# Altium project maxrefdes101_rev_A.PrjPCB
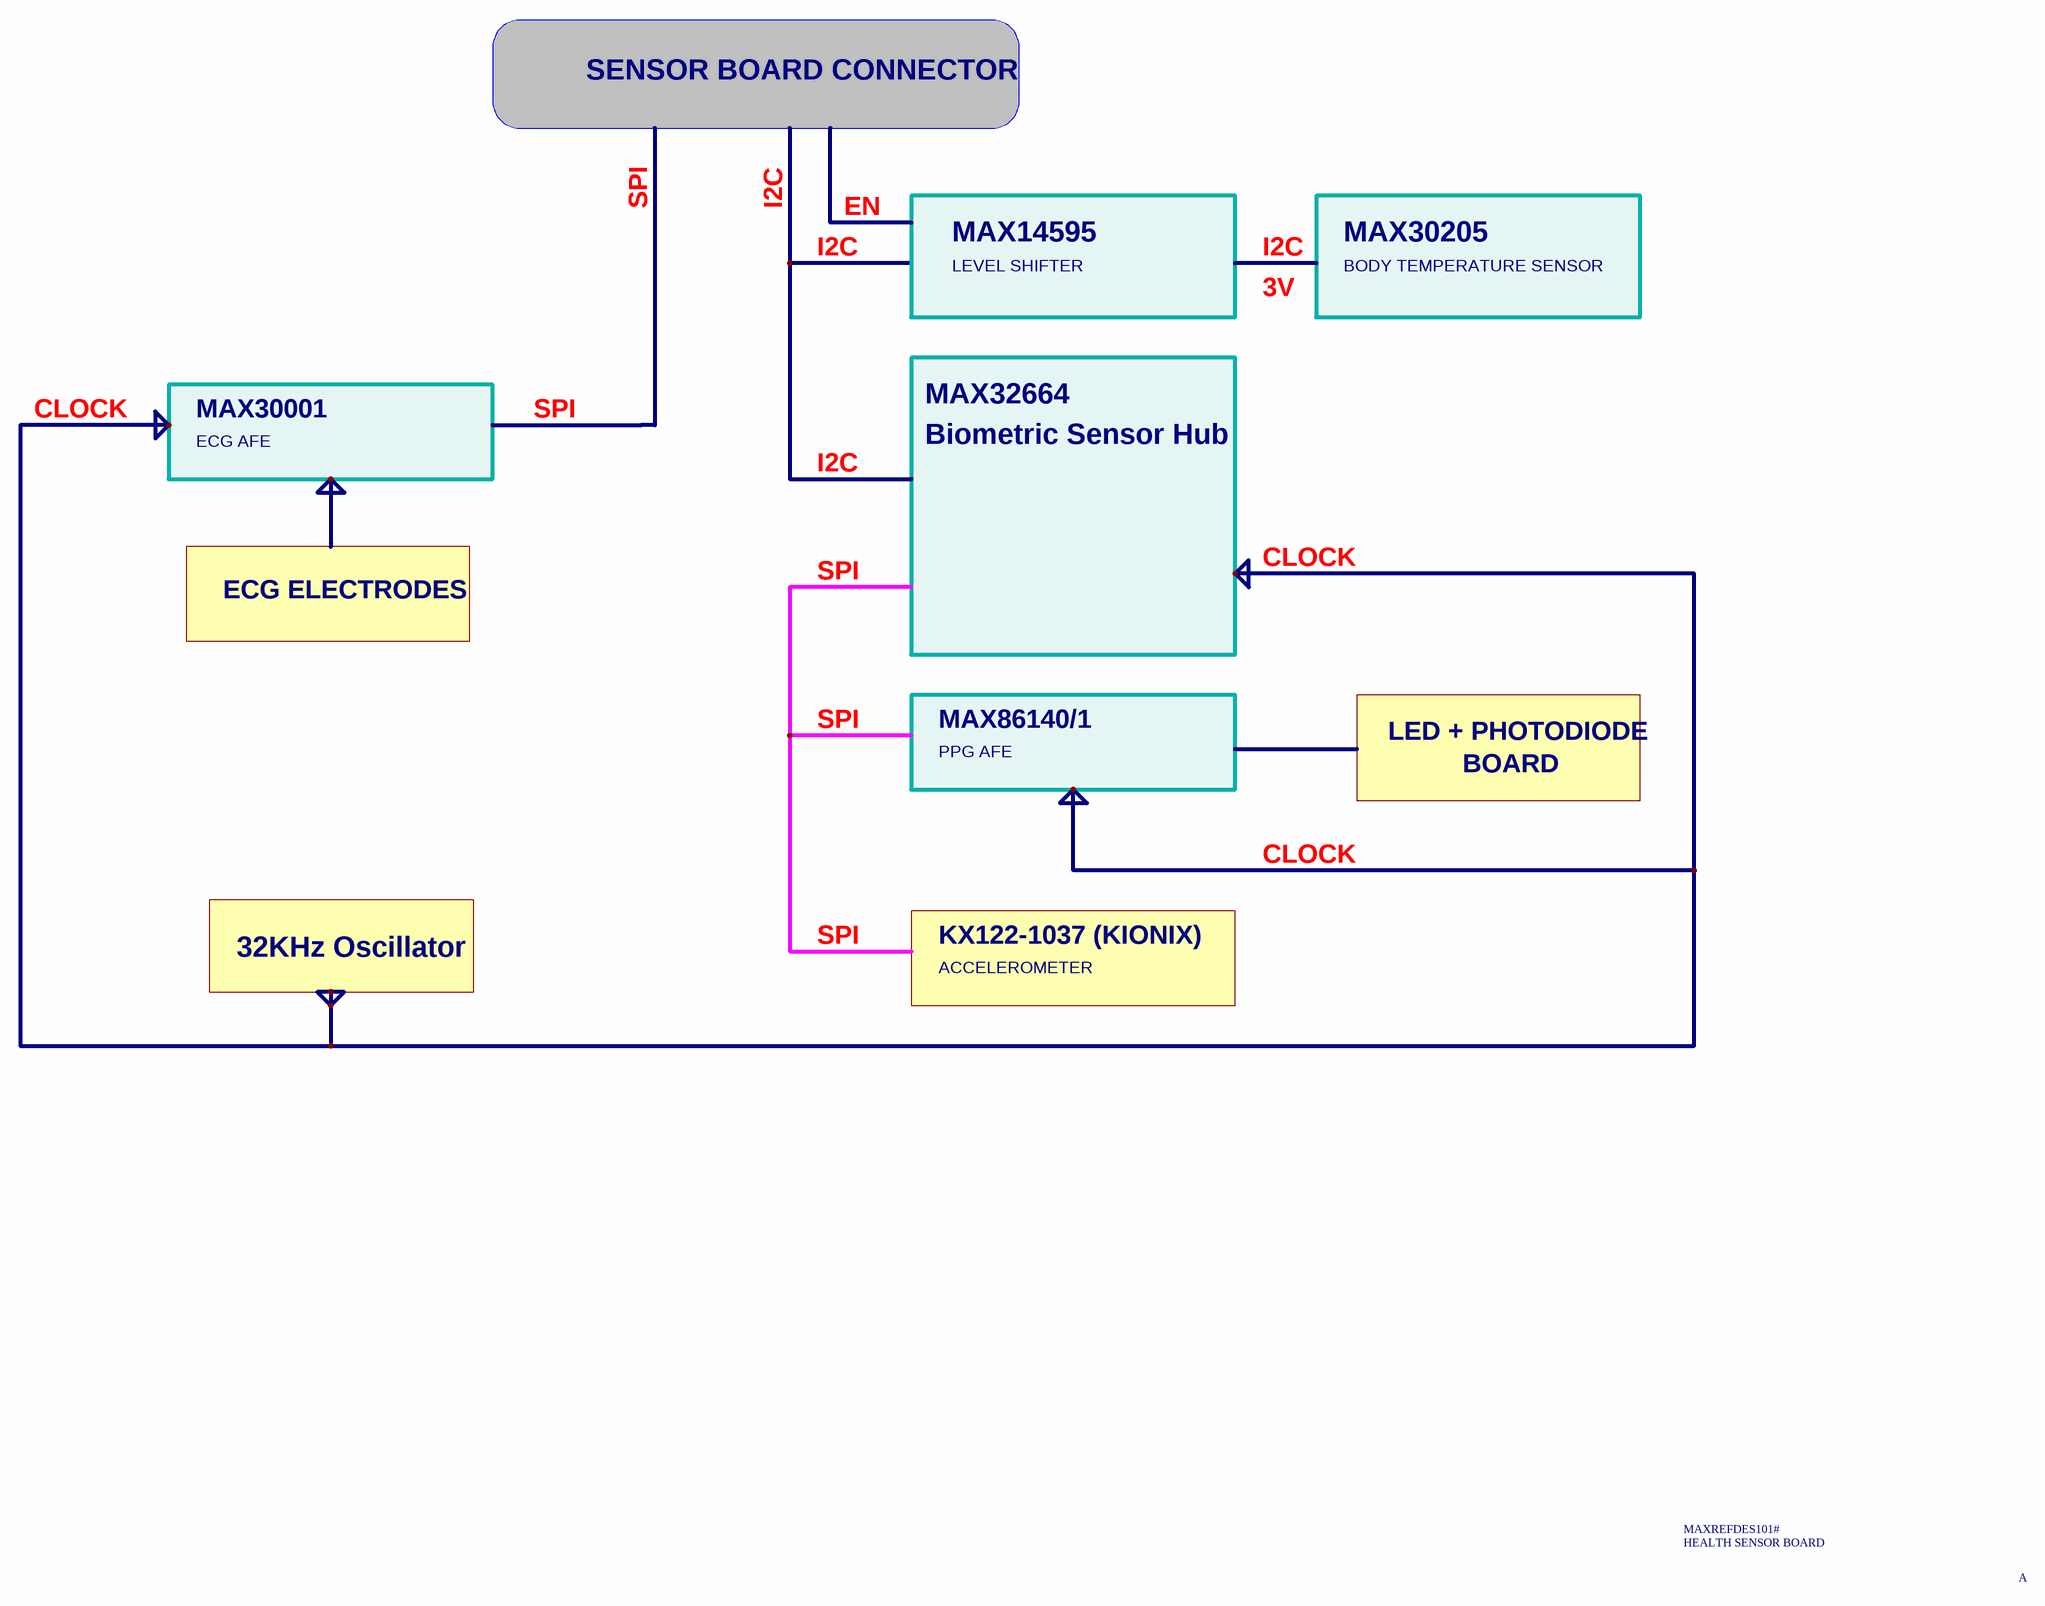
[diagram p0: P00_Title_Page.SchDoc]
2 sheets, 87 parts. Net scope: global (net labels, ports and power ports of the same name join across sheets).
Board file: maxrefdes101_rev_A.PcbDoc
Sheets:
  P00_Title_Page.SchDoc
  P01_Sensors.SchDoc

## Sheet P00_Title_Page.SchDoc
size C; PageSetup: Record=PageOptions¦CenterHorizontal=True¦CenterVertical=True¦PrintScale=0.54¦XCorrection=1.00¦YCorrection=1.00¦PrintKind=1¦BorderSize=5000000¦LeftOffset=0¦BottomOffset=0¦Orientation=2¦PaperLength=1000¦PaperWidth=1000¦Scale=100¦PaperSource=7¦PrintQuality=600¦MediaType=1¦DitherType=10¦PrintScaleMode=1¦PaperKind=Letter¦PaperIndex=1

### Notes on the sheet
- SENSOR BOARD CONNECTOR
- SPI
- I2C
- EN
- MAX14595
- LEVEL SHIFTER
- MAX30205
- BODY TEMPERATURE SENSOR
- 3V
- MAX32664
- CLOCK
- MAX30001
- ECG AFE
- Biometric Sensor Hub
- ECG ELECTRODES
- MAX86140/1
- LED + PHOTODIODE
- PPG AFE
- BOARD
- KX122-1037 (KIONIX)
- 32KHz Oscillator
- ACCELEROMETER
- MAXREFDES101#
- HEALTH SENSOR BOARD
- A

## Sheet P01_Sensors.SchDoc
size C; PageSetup: Record=PageOptions¦CenterHorizontal=True¦CenterVertical=True¦PrintScale=0.54¦XCorrection=1.00¦YCorrection=1.00¦PrintKind=0¦BorderSize=5000000¦LeftOffset=0¦BottomOffset=0¦Orientation=2¦PaperLength=1000¦PaperWidth=1000¦Scale=100¦PaperSource=7¦PrintQuality=-3¦MediaType=1¦DitherType=10¦PrintScaleMode=1¦PaperKind=Letter¦PaperIndex=1
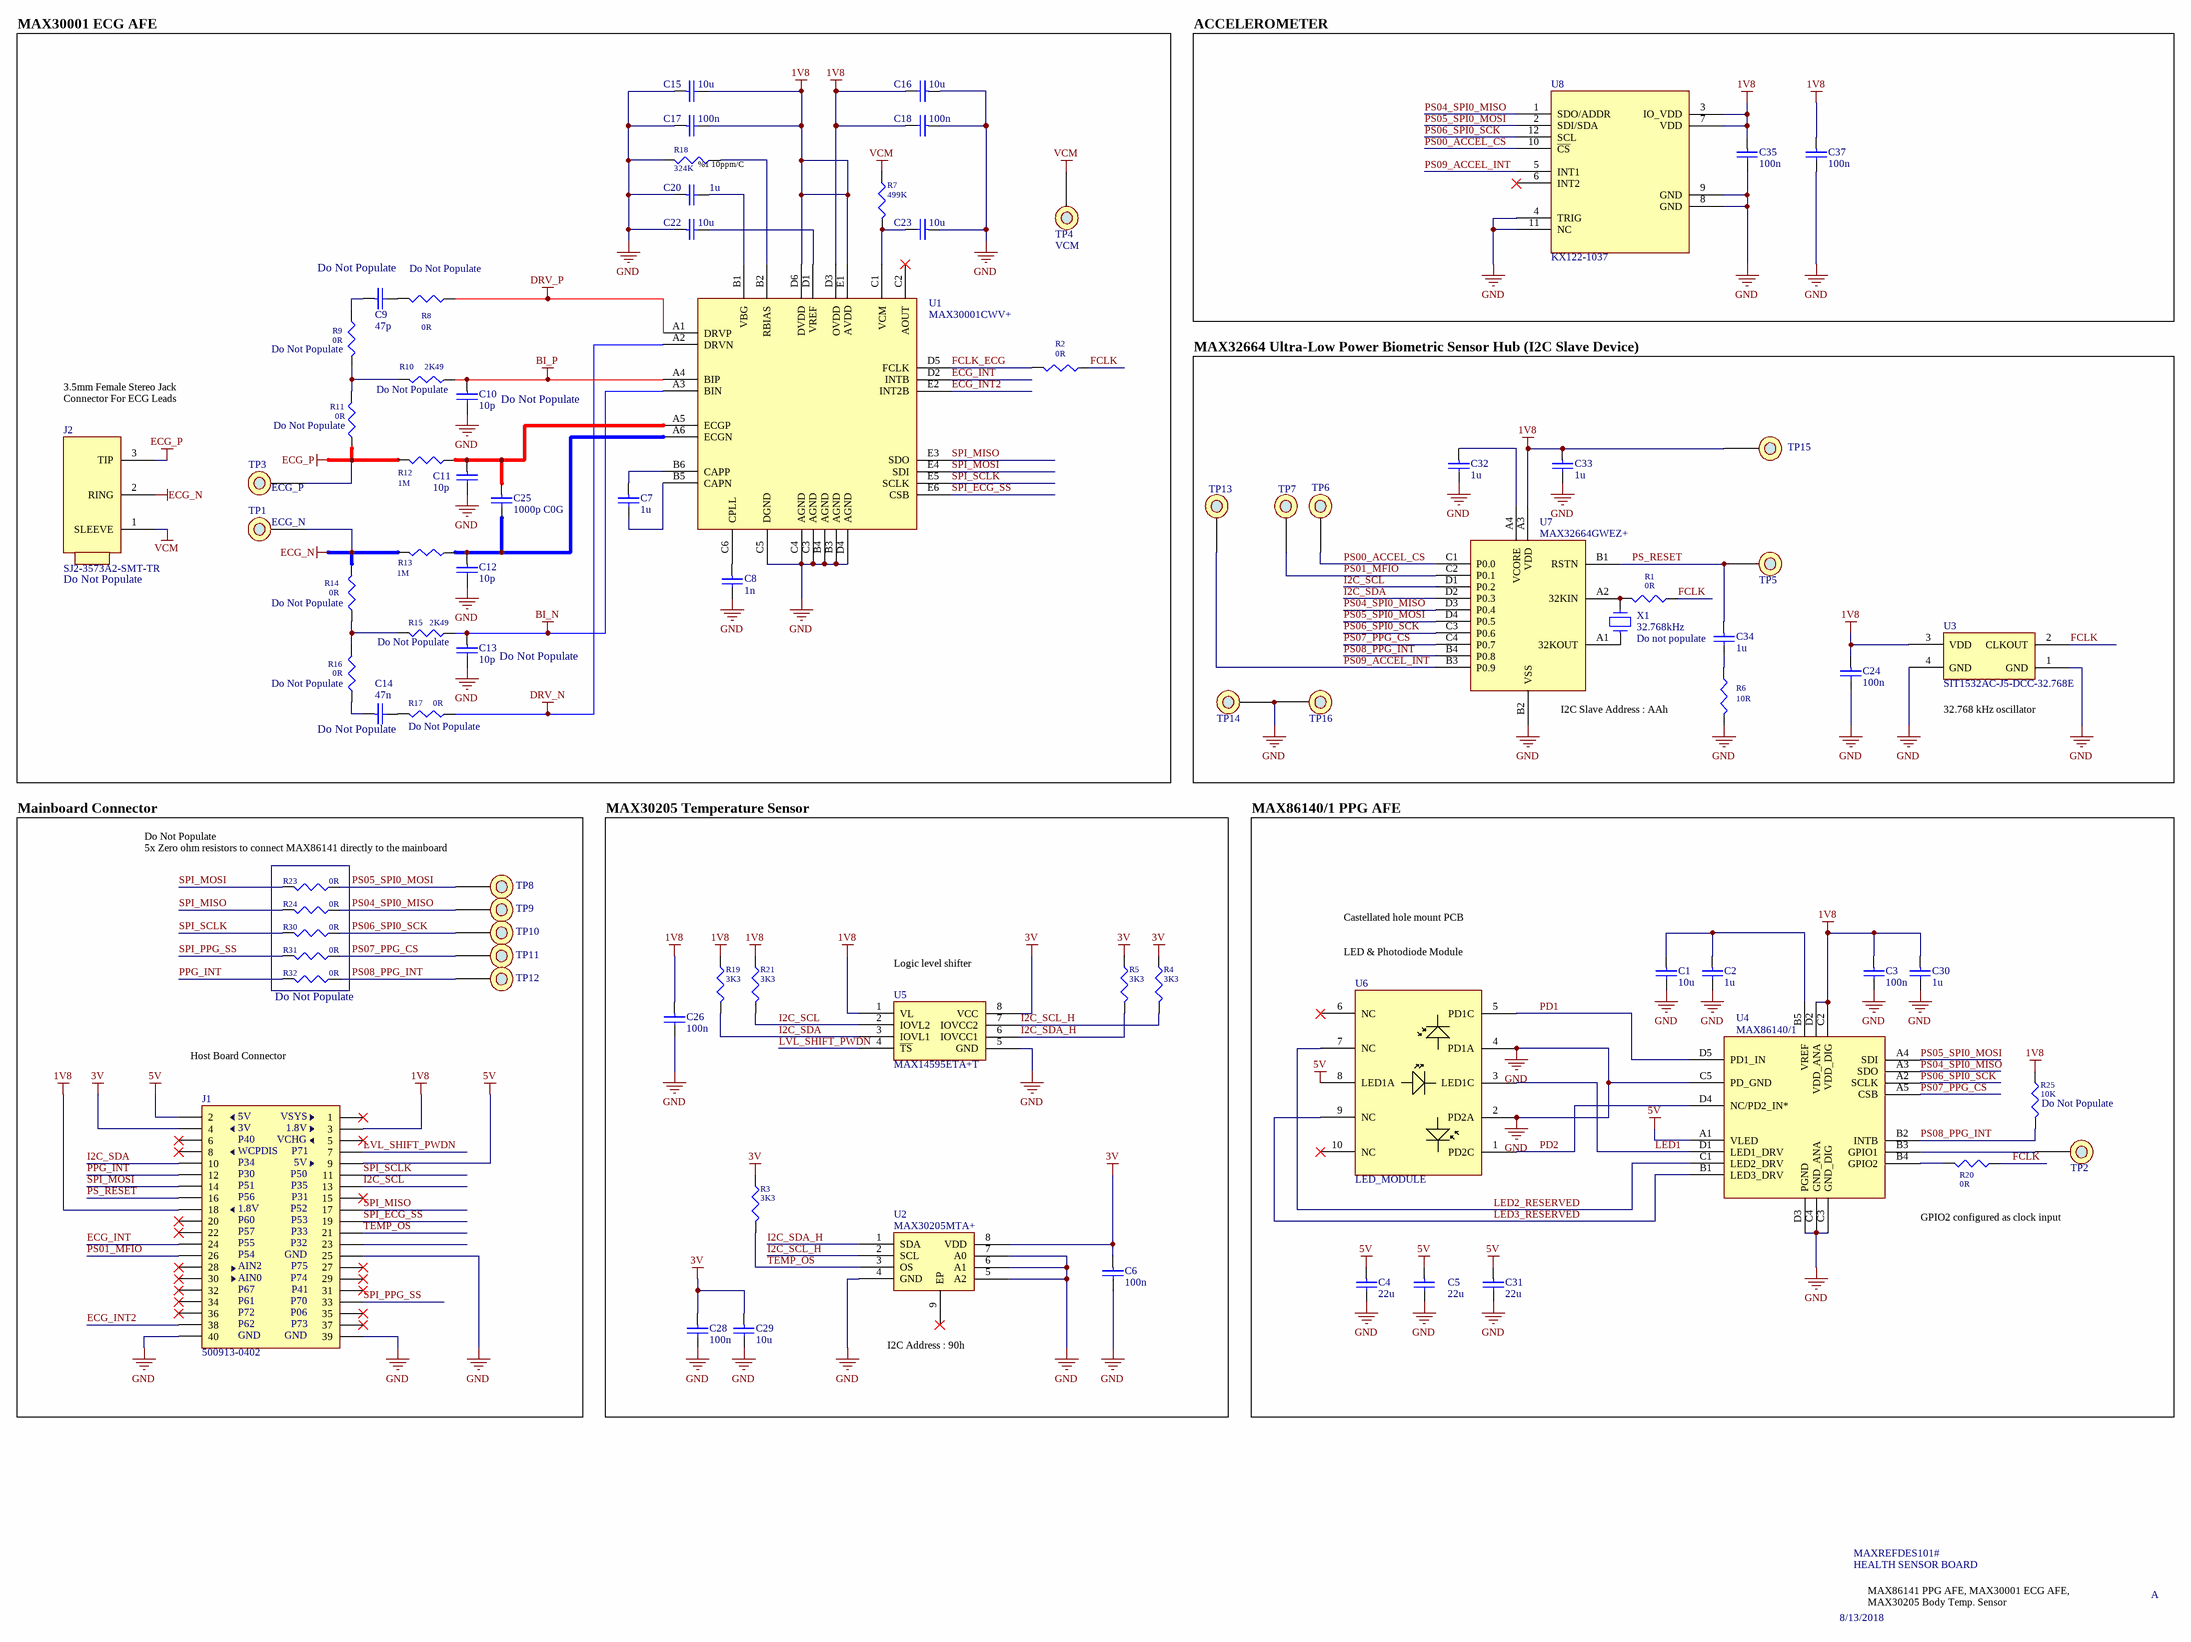
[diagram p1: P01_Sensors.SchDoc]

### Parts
C1  10u  [CAPACITOR_SMD_0402]
C2  1u  [CAPACITOR_SMD_0603]
C3  100n  [CAPACITOR_SMD_0603]
C4  22u  [CAPACITOR_SMD_0402]
C5  22u  [CAPACITOR_SMD_0402]
C6  100n  [CAPACITOR_SMD_0402]
C7  1u  [CAPACITOR_SMD_0603]
C8  1n  [CAPACITOR_SMD_0201]
C9  47p  [CAPACITOR_SMD_0201]
C10  10p  [CAPACITOR_SMD_0201]
C11  10p  [CAPACITOR_SMD_0201]
C12  10p  [CAPACITOR_SMD_0201]
C13  10p  [CAPACITOR_SMD_0201]
C14  47n  [CAPACITOR_SMD_0201]
C15  10u  [CAPACITOR_SMD_0402]
C16  10u  [CAPACITOR_SMD_0402]
C17  100n  [CAPACITOR_SMD_0201]
C18  100n  [CAPACITOR_SMD_0201]
C20  1u  [CAPACITOR_SMD_0201]
C22  10u  [CAPACITOR_SMD_0402]
C23  10u  [CAPACITOR_SMD_0402]
C24  100n  [CAPACITOR_SMD_0402]
C25  1000p C0G  [CAPACITOR_SMD_0201]
C26  100n  [CAPACITOR_SMD_0402]
C28  100n  [CAPACITOR_SMD_0402]
C29  10u  [CAPACITOR_SMD_0402]
C30  1u  [CAPACITOR_SMD_0201]
C31  22u  [CAPACITOR_SMD_0402]
C32  1u  [CAPACITOR_SMD_0201]
C33  1u  [CAPACITOR_SMD_0201]
C34  1u  [CAPACITOR_SMD_0201]
C35  100n  [CAPACITOR_SMD_0201]
C37  100n  [CAPACITOR_SMD_0201]
J1  500913-0402  [500913-0402_MRR]
J2  SJ2-3573A2-SMT-TR  [CONN_SJ2-3573A2-SMT-TR]
R1  0R  [RESISTOR_SMD_0201]
R2  0R  [RESISTOR_SMD_0201]
R3  3K3  [RESISTOR_SMD_0402]
R4  3K3  [RESISTOR_SMD_0402]
R5  3K3  [RESISTOR_SMD_0402]
R6  10R  [RESISTOR_SMD_0201]
R7  499K  [RESISTOR_SMD_0402]
R8  0R  [RESISTOR_SMD_0201]
R9  0R  Notes: Do Not Populate  [RESISTOR_SMD_0201]
R10  2K49  Notes: Do Not Populate  [RESISTOR_SMD_0201]
R11  0R  Notes: Do Not Populate  [RESISTOR_SMD_0201]
R12  1M  [RESISTOR_SMD_0201]
R13  1M  [RESISTOR_SMD_0201]
R14  0R  Notes: Do Not Populate  [RESISTOR_SMD_0201]
R15  2K49  Notes: Do Not Populate  [RESISTOR_SMD_0201]
R16  0R  Notes: Do Not Populate  [RESISTOR_SMD_0201]
R17  0R  Notes: Do Not Populate  [RESISTOR_SMD_0201]
R18  324K  [RESISTOR_SMD_0603]
R19  3K3  [RESISTOR_SMD_0402]
R20  0R  [RESISTOR_SMD_0201]
R21  3K3  [RESISTOR_SMD_0402]
R23  0R  [RESISTOR_SMD_0201]
R24  0R  [RESISTOR_SMD_0201]
R25  10K  Notes: Do Not Populate  [RESISTOR_SMD_0201]
R30  0R  [RESISTOR_SMD_0201]
R31  0R  [RESISTOR_SMD_0201]
R32  0R  [RESISTOR_SMD_0201]
TP1  ECG_N  [TESTPOINT_SIZE_A_NO_BODY]
TP2  TestPoint  [TESTPOINT_SIZE_B]  (value not drawn)
TP3  ECG_P  [TESTPOINT_SIZE_A_NO_BODY]
TP4  VCM  [TESTPOINT_SIZE_A_NO_BODY]
TP5  RSTN  [TESTPOINT_SIZE_C]  (value not drawn)
TP6  TestPoint  [TESTPOINT_SIZE_C]  (value not drawn)
TP7  TestPoint  [TESTPOINT_SIZE_C]  (value not drawn)
TP8  TestPoint  [TESTPOINT_SIZE_B]  (value not drawn)
TP9  TestPoint  [TESTPOINT_SIZE_B]  (value not drawn)
TP10  TestPoint  [TESTPOINT_SIZE_B]  (value not drawn)
TP11  TestPoint  [TESTPOINT_SIZE_B]  (value not drawn)
TP12  TestPoint  [TESTPOINT_SIZE_B]  (value not drawn)
TP13  TestPoint  [TESTPOINT_SIZE_B]  (value not drawn)
TP14  TestPoint  [TESTPOINT_SIZE_B]  (value not drawn)
TP15  TestPoint  [TESTPOINT_SIZE_C]  (value not drawn)
TP16  TestPoint  [TESTPOINT_SIZE_B]  (value not drawn)
U1  MAX30001CWV+  [WLP30 0.5MM]
U2  MAX30205MTA+  [TDFN_3x3mm]
U3  SIT1532AC-J5-DCC-32.768E  [CSP_1.55x0.85_4pin]
U4  MAX86140/1  [WLP20_0.4mm]
U5  MAX14595ETA+T  [TDFN8]
U6  LED_MODULE  [HSP3_LEDMODULE_03]
U7  MAX32664GWEZ+  [WLP16_0.35mm]
U8  KX122-1037  [LGA-12_2x2x0.9]
X1  32.768kHz  Notes: Do not populate  [CRYSTAL_2x1.2mm]

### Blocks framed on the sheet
MAX30001 ECG AFE: C7-C18 C20 C22 C23 C25 J2 R2 R7-R18 TP1 TP3 TP4 U1
ACCELEROMETER: C35 C37 U8
Mainboard Connector: J1 R23 R24 R30-R32 TP8-TP12
MAX30205 Temperature Sensor: C6 C26 C28 C29 R3-R5 R19 R21 U2 U5
MAX86140/1 PPG AFE: C1-C5 C30 C31 R20 R25 TP2 U4 U6

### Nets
1V8: C3.1 C15.2 C16.2 C17.2 C18.2 C24.1 C26.1 C30.1 C33.1 C35.1 C37.1 J1.3 J1.18 R19.1 R21.1 R25.1 TP15.TP U1.D3(OVDD) U1.D6(DVDD) U1.E1(AVDD) U3.3(VDD) U4.C2(VDD_DIG) U4.D2(VDD_ANA) U5.1(VL) U7.A3(VDD) U8.3(IO_VDD) U8.7(VDD)
3V: C6.1 C28.1 C29.1 J1.4 R3.1 R4.1 R5.1 U2.8(VDD) U5.8(VCC)
5V: C4.1 C5.1 C31.1 J1.2 J1.9 U4.A1(VLED) U6.8(LED1A)
BI_N: C13.1 R15.1 U1.A3(BIN)
BI_P: C10.1 R10.1 U1.A4(BIP)
DRV_N: R17.1 U1.A2(DRVN)
DRV_P: R8.1 U1.A1(DRVP)
ECG_N: J2.2(RING) R13.2 R14.2 TP1.TP
ECG_P: J2.3(TIP) R11.1 R12.2 TP3.TP
GND: C1.2 C2.2 C3.2 C4.2 C5.2 C6.2 C8.2 C10.2 C11.2 C12.2 C13.2 C15.1 C16.1 C17.1 C18.1 C20.1 C22.1 C23.1 C24.2 C26.2 C28.2 C29.2 C30.2 C31.2 C32.2 C33.2 C35.2 C37.2 J1.25 J1.39 J1.40 R6.2 R18.2 TP14.TP TP16.TP U1.B3(AGND) U1.B4(AGND) U1.C3(AGND) U1.C4(AGND) U1.C5(DGND) U1.D4(AGND) U2.4(GND) U2.5(A2) U2.6(A1) U2.7(A0) U3.1(GND) U3.4(GND) U4.C3(GND_DIG) U4.C4(GND_ANA) U4.C5(PD_GND) U4.D3(PGND) U5.5(GND) U6.2(PD2A) U6.4(PD1A) U7.B2(VSS) U8.4(TRIG) U8.8(GND) U8.9(GND) U8.11(NC)
VCM: J2.1(SLEEVE) R7.1 TP4.TP
ECG_INT: J1.24 U1.D2(INTB)
ECG_INT2: J1.38 U1.E2(INT2B)
FCLK: R1.1 R2.1 R20.1 U3.2(CLKOUT)
FCLK_ECG: R2.2 U1.D5(FCLK)
I2C_SCL: J1.13 R21.2 U5.2(IOVL2) U7.D1(P0.2)
I2C_SCL_H: R4.2 U2.2(SCL) U5.7(IOVCC2)
I2C_SDA: J1.10 R19.2 U5.3(IOVL1) U7.D2(P0.3)
I2C_SDA_H: R5.2 U2.1(SDA) U5.6(IOVCC1)
LED1: U4.D1(LED1_DRV) U6.3(LED1C)
LED2_RESERVED: U4.C1(LED2_DRV) U6.7(NC)
LED3_RESERVED: U4.B1(LED3_DRV) U6.9(NC)
LVL_SHIFT_PWDN: J1.7 U5.4(~{TS})
PD1: U4.D5(PD1_IN) U6.5(PD1C)
PD2: U4.D4(NC/PD2_IN*) U6.1(PD2C)
PPG_INT: J1.12 R32.2
PS00_ACCEL_CS: TP6.TP U7.C1(P0.0) U8.10(~{CS})
PS01_MFIO: J1.26 TP7.TP U7.C2(P0.1)
PS04_SPI0_MISO: R24.1 TP9.TP U4.A3(SDO) U7.D3(P0.4) U8.1(SDO/ADDR)
PS05_SPI0_MOSI: R23.1 TP8.TP U4.A4(SDI) U7.D4(P0.5) U8.2(SDI/SDA)
PS06_SPI0_SCK: R30.1 TP10.TP U4.A2(SCLK) U7.C3(P0.6) U8.12(SCL)
PS07_PPG_CS: R31.1 TP11.TP U4.A5(CSB) U7.C4(P0.7)
PS08_PPG_INT: R25.2 R32.1 TP12.TP U4.B2(INTB) U7.B4(P0.8)
PS09_ACCEL_INT: TP13.TP U7.B3(P0.9) U8.5(INT1)
PS_RESET: C34.1 J1.16 TP5.TP U7.B1(RSTN)
SPI_ECG_SS: J1.19 U1.E6(CSB)
SPI_MISO: J1.17 R24.2 U1.E3(SDO)
SPI_MOSI: J1.14 R23.2 U1.E4(SDI)
SPI_PPG_SS: J1.33 R31.2
SPI_SCLK: J1.11 R30.2 U1.E5(SCLK)
TEMP_OS: J1.21 R3.2 U2.3(OS)
NetC1_1: C1.1 C2.1 U4.B5(VREF)
NetC7_1: C7.1 U1.B6(CAPP)
NetC7_2: C7.2 U1.B5(CAPN)
NetC8_1: C8.1 U1.C6(CPLL)
NetC9_1: C9.1 R9.1
NetC9_2: C9.2 R8.2
NetC11_1: C11.1 C25.1 R12.1 U1.A5(ECGP)
NetC12_1: C12.1 C25.2 R13.1 U1.A6(ECGN)
NetC14_1: C14.1 R16.1
NetC14_2: C14.2 R17.2
NetC20_2: C20.2 U1.B1(VBG)
NetC22_2: C22.2 U1.D1(VREF)
NetC23_2: C23.2 R7.2 U1.C1(VCM)
NetC32_1: C32.1 U7.A4(VCORE)
NetC34_2: C34.2 R6.1
NetR1_2: R1.2 U7.A2(32KIN) X1.2
NetR9_2: R9.2 R10.2 R11.2
NetR14_1: R14.1 R15.2 R16.2
NetR18_1: R18.1 U1.B2(RBIAS)
NetR20_2: R20.2 U4.B4(GPIO2)
NetTP2_TP: TP2.TP U4.B3(GPIO1)
NetU7_A1: U7.A1(32KOUT) X1.1

Not connected (* = marked no-connect by the designer): J1 1* 5* 6* 8* 15* 20* 22* 23 27* 28* 29* 30* 31* 32* 34* 35* 36* 37*; U1 C2(AOUT)*; U2 9(EP)*; U6 6(NC)* 10(NC)*; U8 6(INT2)*

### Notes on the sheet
- (near R18) %1 10ppm/C
- Do Not Populate
- MAX32664 Ultra-Low Power Biometric Sensor Hub (I2C Slave Device)
- 3.5mm Female Stereo Jack Connector For ECG Leads
- (near C10) Do Not Populate
- (near J2) Do Not Populate
- (near C13) Do Not Populate
- (near U7) I2C Slave Address : AAh
- (near U3) 32.768 kHz oscillator
- Do Not Populate
  5x Zero ohm resistors to connect MAX86141 directly to the mainboard
- Castellated hole mount PCB
- (near R32) Do Not Populate
- (near U5) Logic level shifter
- LED & Photodiode Module
- (near J1) Host Board Connector
- GPIO2 configured as clock input
- I2C Address : 90h
- MAXREFDES101#
- HEALTH SENSOR BOARD
- 8/13/2018
- MAX86141 PPG AFE, MAX30001 ECG AFE, MAX30205 Body Temp. Sensor
- A

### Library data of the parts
C1 C15 C16 C22 C23 C29 = CAP_0402_10u: CAP CER 10UF 4V X5R 0402; Manufacturer: Murata Electronics North America; Manufacturer Part Number: GRM155R60G106ME44D
C2 C7 = CAP_0603_1u: CAP CER 1UF 16V X5R 0603; Manufacturer: Murata Electronics North America; Manufacturer Part Number: GRM188R61C105KA12D
C3 = CAP_0603_100n: CAP CER 0.1UF 16V X7R 0603; Manufacturer: Murata Electronics North America; Manufacturer Part Number: GRM188R71C104KA01D
C4 C5 C31 = CAP_0402_22U: CAP CER 22UF 6.3V X5R 0402; Manufacturer: Samsung Electro-Mechanics; Manufacturer Part Number: CL05A226MQ5N6J8
C6 C24 C26 C28 = CAP_0402_100n: CAP CER 0.1UF 16V X7R 0402; Manufacturer: Murata Electronics North America; Manufacturer Part Number: GRM155R71C104KA88D
C8 = CAP_0201_1n: CAP CER 1000PF 16V X7R 0201; Manufacturer: Murata Electronics North America; Manufacturer Part Number: GRM033R71C102KA01D
C9 = CAP_0201_47p: CAP CER 47PF 25V C0G/NP0 0201; Manufacturer: Murata Electronics North America; Manufacturer Part Number: GRM0335C1E470FA01D
C10-C13 = CAP_0201_10p: CAP CER 10PF 25V C0G/NP0 0201; Manufacturer: Murata Electronics North America; Manufacturer Part Number: GRM0335C1E100FA01D
C14 = CAP_0201_47n: CAP CER 0.047UF 16V X5R 0201; Manufacturer: Murata Electronics North America; Manufacturer Part Number: GRM033R61C473ME84D
C17 C18 C35 C37 = CAP_0201_100n: CAP CER 0.1UF 10V X5R 0201; Manufacturer: Murata Electronics North America; Manufacturer Part Number: GRM033R61A104KE15D
C20 C30 C32-C34 = CAP_0201_1u: CAP CER 1UF 10V X6S 0201; Manufacturer: Murata Electronics North America; Manufacturer Part Number: GRM033C81A105ME05D
C25 = CAP_0201_1000p: CAP CER 1000PF 25V C0G/NP0 0201; Manufacturer: Murata Electronics North America; Manufacturer Part Number: TMK063CG102JT-F
J1 = MOLEX_5009130402: CONN RCPT 40POS 0.4MM SMD GOLD; Manufacturer: Molex
J2 = SJ2-3573A2-SMT-TR: AUDIO JACK, 3.5 MM, RT, 3 CONDUC; Manufacturer: CUI Inc.
R1 R2 R8 R9 R11 R14 R16 R17 R20 = RES_0201_0R: RES SMD 0 OHM JUMPER 1/20W 0201; Manufacturer: Panasonic Electronic Components; Manufacturer Part Number: ERJ-1GN0R00C
R3-R5 R19 R21 = RES_0402_3K3: RES SMD 3.3K OHM 1% 1/10W 0402; Manufacturer: Panasonic Electronic Components; Manufacturer Part Number: ERJ-2RKF3301X
R6 = RES_0201_10R: RES SMD 10 OHM 1% 1/20W 0201; Manufacturer: Panasonic Electronic Components; Manufacturer Part Number: ERJ-1GEF10R0C
R7 = RES_0402_499K: RES SMD 49.9K OHM 1% 1/10W 0402; Manufacturer: Panasonic Electronic Components; Manufacturer Part Number: ERJ-2RKF4993X
R10 R15 = RES_0201_2K49: RES SMD 2.49K OHM 1% 1/20W 0201; Manufacturer: Panasonic Electronic Components; Manufacturer Part Number: ERJ-1GEF2491C
R12 R13 = RES_0201_1M: RES SMD 1M OHM 1% 1/20W 0201; Manufacturer: Panasonic Electronic Components; Manufacturer Part Number: P122656CT-ND
R18 = RES_0603_324K%0.1_10ppm: RES SMD 324K OHM 0.1% 1/16W 0603; Manufacturer: TE Connectivity Passive Product; Manufacturer Part Number: A124738CT-ND
R23 R24 R30-R32 = RES_0201_0R: RES SMD 0 OHM JUMPER 1/20W 0201; Manufacturer: Panasonic Electronic Components; Manufacturer Part Number: ERJ-1GN0R00C; Notes: Do Not Populate
R25 = RES_0201_10K: RES SMD 10K OHM 1% 1/20W 0201; Manufacturer: Panasonic Electronic Components; Manufacturer Part Number: ERJ-1GEF1002C
TP1-TP5 = TestPoint: PCB Pad Test Point
TP6-TP16 = TestPoint: PCB Pad Test Point; Notes: DNI
U1 = MAX30001CWV+: Ultra-Low Power Single Channel Integrated Biopotential (ECG, Pace, R-R Detection) and Bioimpedance (BioZ) AFE; Manufacturer: Maxim Intergrated
U2 = MAX30205MTA+: Human Body Temperature Sensor; Manufacturer: Maxim Integrated
U3 = SIT1532AC-J5-DCC-32.768E: OSC MEMS 32.768KHZ LVCMOS SMD; Manufacturer: SiTIME
U4 = MAX86140/1: Best-in-Class Optical Pulse Oximeter and Heart Rate Sensor for Wearable Health; Manufacturer: Maxim Integrated; Manufacturer Part Number: MAX86140 or MAX86141
U5 = MAX14595ETA+T: Low-Power Dual-Channel Logic-Level Translator; Manufacturer: Maxim Integrated
U6 = HSP3_LEDMODULE_03: MAXREFDES101 LED Module v4 PCB; Manufacturer: Maxim Integrated; Manufacturer Part Number: MAXREFDES101LEDV4
U7 = MAX32660GWE+: Ultra-Low Power Biometric Sensor Hub; Manufacturer: Maxim Integrated
U8 = KX122-1037: ACCELEROMETER 2-8G I2C/SPI 12LGA; Manufacturer: Kionix Inc.
X1 = CRYSTAL_ABS06-107-32.768KHZ-T: CRYSTAL 32.7680KHZ 4PF SMD; Manufacturer: Abracon Corporation

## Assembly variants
DEFAULT_KX122: not fitted C9 C10 C13 C14 J2 R8 R9 R10 R11 R14 R15 R16 R17 R23 R24 R25 R30 R31 R32 TP1 TP2 TP3 TP4 TP5 TP6 TP7 TP8 TP9 TP10 TP11 TP12 TP13 TP14 TP15 TP16 X1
